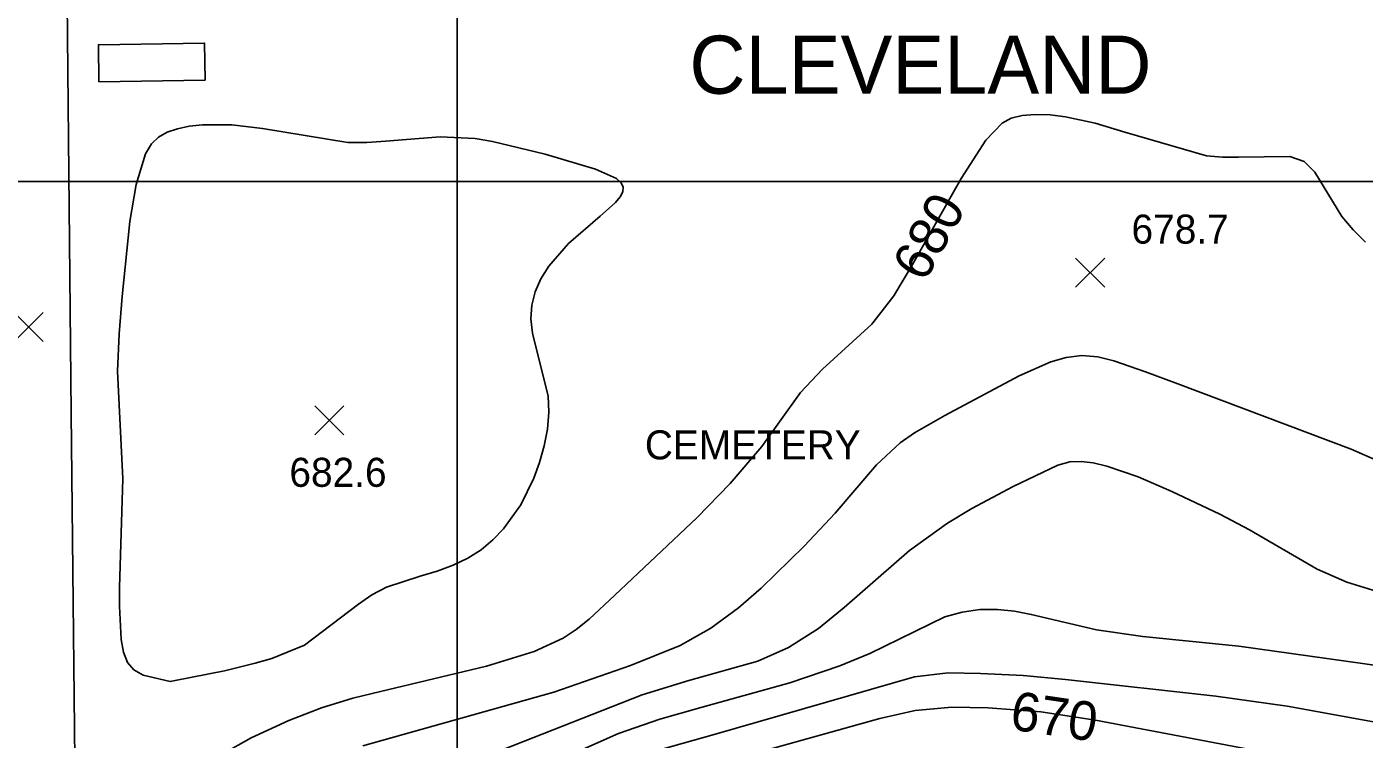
# Model space of a CAD drawing. Extents: x 79600 to 91800, y 75600 to 84400.
# Drawn here: x 80778 to 81468, y 78712 to 79080 of the extents above; entities that cross this region are included whole.
import ezdxf

# ---------------------------------------------------------------- set-up
doc = ezdxf.new("R2010")
doc.units = 0
for name, color, linetype in [('080-085$0$BLDG', 7, 'Continuous'), ('080-085$0$CITY-NAME', 7, 'Continuous'), ('080-085$0$GRID', 7, 'Continuous'), ('080-085$0$INDEX', 7, 'Continuous'), ('080-085$0$INDXLBL', 7, 'Continuous'), ('080-085$0$INTER', 7, 'Continuous'), ('080-085$0$ROAD', 7, 'Continuous'), ('080-085$0$ROAD-NAME', 7, 'Continuous'), ('080-085$0$SPOTMARK', 7, 'Continuous'), ('080-085$0$SPOTS', 7, 'Continuous')]:
    doc.layers.add(name, color=color, linetype=linetype)

# ---------------------------------------------------------------- blocks, each defined once
blk = doc.blocks.new('080-085$0$SPOTS')
at = {"layer": '080-085$0$SPOTMARK'}
for p, q in [((-0.5, -0.5), (0.5, 0.5)), ((-0.5, 0.5), (0.5, -0.5))]:
    blk.add_line(p, q, dxfattribs=at)

msp = doc.modelspace()

# ---------------------------------------------------------------- linework, layer by layer
at = {"layer": '080-085$0$BLDG'}
msp.add_lwpolyline([(80869.76, 79052.42), (80814.93, 79051.58), (80814.64, 79070.71), (80869.47, 79071.55)], close=True, dxfattribs=at)
at = {"layer": '080-085$0$GRID'}
for p, q in [((81000, 80000), (81000, 76000)), ((85000, 79000), (80000, 79000))]:
    msp.add_line(p, q, dxfattribs=at)
at = {"layer": '080-085$0$INDEX'}
for points in [[(81468.93, 78968.77), (81462.51, 78975.14), (81456.65, 78982.05), (81442.84, 79004.95), (81437.28, 79010.4), (81429.83, 79013.02), (81403.43, 79012.61), (81395.11, 79012.62), (81386.77, 79013.39), (81344.64, 79025.52), (81329.28, 79030.14), (81313.97, 79033.52), (81306.04, 79034.44), (81298.38, 79034.69), (81291.58, 79034.15), (81286.04, 79032.7), (81281.42, 79030.18), (81272.9, 79021.34), (81260.14, 79001.68), (81235.02, 78957.13), (81225.32, 78941.03), (81214.04, 78926.43), (81188.5, 78903.15), (81177.14, 78891.11), (81157.18, 78863.17), (81140.89, 78844.15), (81123.63, 78826.43), (81081.25, 78786.47), (81068.07, 78773.95), (81061.45, 78768.7), (81054.67, 78764.25), (81039.72, 78757.27), (81015.08, 78749.67), (80960.34, 78736.59), (80946.04, 78733.16), (80929.87, 78728.24), (80912.97, 78721.72), (80893.61, 78712.72), (80865.53, 78696.92)], [(81431.15, 78702.63), (81329.57, 78721.79), (81301.32, 78726.15), (81274.15, 78728.23), (81255.41, 78728.59), (81236.36, 78726.78), (81218.14, 78722.75), (81130.54, 78698.26)]]:
    msp.add_lwpolyline(points, dxfattribs=at)
at = {"layer": '080-085$0$INTER'}
msp.add_lwpolyline([(80854.34, 78742.28), (80879.81, 78747.39), (80895.7, 78751.36), (80904.24, 78753.77), (80921.11, 78760.51), (80948.96, 78781.69), (80955.85, 78786.54), (80963.41, 78790.59), (80980.81, 78796.29), (80989.65, 78798.85), (80997.89, 78801.86), (81005.44, 78805.48), (81012.28, 78809.84), (81018.42, 78814.98), (81023.88, 78820.71), (81032.78, 78833), (81039.59, 78846.83), (81042.48, 78854.87), (81044.88, 78863.46), (81046.54, 78872.23), (81047.27, 78880.86), (81046.98, 78889.33), (81040.78, 78914.03), (81038.75, 78921.79), (81037.93, 78929.17), (81038.42, 78936.22), (81040.18, 78943.09), (81043.17, 78949.83), (81047.19, 78956.34), (81057.46, 78968.1), (81073.84, 78982.09), (81081.75, 78989.21), (81084.13, 78992.13), (81085.39, 78994.72), (81085.56, 78997.09), (81084.59, 78999.34), (81082.16, 79001.58), (81071.4, 79006.4), (81045.41, 79014.13), (81018.12, 79020.7), (81009.16, 79022.22), (80991.13, 79023.2), (80962.94, 79020.93), (80953.21, 79020.28), (80943.46, 79020.28), (80899.37, 79027.49), (80883.64, 79029.31), (80868.4, 79029.4), (80861.56, 79028.65), (80855.45, 79027.36), (80850.17, 79025.51), (80845.76, 79023.03), (80842.11, 79019.47), (80839.04, 79014.29), (80834.22, 78998.53), (80830.97, 78979.36), (80826.97, 78940.75), (80825.45, 78921.41), (80824.58, 78902.15), (80827.24, 78846.44), (80825.62, 78790.39), (80825.58, 78780.72), (80826.49, 78763.5), (80827.63, 78756.88), (80829.65, 78751.69), (80832.99, 78747.81), (80837.81, 78745.12), (80851.71, 78741.86)], close=True, dxfattribs=at)
for points in [[(81492.49, 78848.14), (81461.59, 78861.87), (81372.02, 78895.56), (81355.42, 78901.77), (81338.98, 78907.42), (81330.67, 78909.45), (81322.45, 78910.19), (81314.4, 78909.24), (81306.42, 78906.88), (81290.17, 78899.75), (81251.77, 78879.26), (81236.08, 78870.18), (81228.72, 78865.09), (81216.38, 78853.69), (81195.19, 78828.77), (81179.13, 78811.63), (81156.97, 78790.05), (81145.22, 78779.81), (81130.96, 78769.31), (81115.09, 78760.34), (81089.47, 78750.1), (81049.84, 78736.28), (80951.16, 78708.5)], [(81475.02, 78788.31), (81459.26, 78793.06), (81443.96, 78799.91), (81408.97, 78820.12), (81393.68, 78828.31), (81369, 78840.02), (81351.59, 78847.48), (81335.33, 78853), (81328.29, 78854.68), (81322.15, 78855.48), (81316.34, 78855.19), (81310.09, 78853.6), (81287, 78842.58), (81265.67, 78831.13), (81253.1, 78823.6), (81233.49, 78809.42), (81199.67, 78780.02), (81186.42, 78769.2), (81170.97, 78759.37), (81155.22, 78752.35), (81119.49, 78742.32), (81095.44, 78735), (81023.69, 78706.74)], [(81477.18, 78749.67), (81403.53, 78760.14), (81353.93, 78765.09), (81329.98, 78768.55), (81296.38, 78776.45), (81287.71, 78778.06), (81278.87, 78779), (81269.85, 78778.94), (81260.7, 78777.66), (81251.68, 78775.29), (81213.06, 78756.33), (81197.5, 78749.88), (81171.73, 78741.04), (81126.44, 78728.52), (81104.61, 78722.28), (81083.22, 78714.98), (81017.6, 78685.84)], [(81526.75, 78711.46), (81522.15, 78714.26), (81480.69, 78719.67), (81428.46, 78728.99), (81391.62, 78734.22), (81314.06, 78742.86), (81292.16, 78744.88), (81270.2, 78746.03), (81253.4, 78746.21), (81236.04, 78744.25), (81132.66, 78714.51), (81099.62, 78705.21)]]:
    msp.add_lwpolyline(points, dxfattribs=at)
at = {"layer": '080-085$0$ROAD'}
msp.add_lwpolyline([(80803.08, 78652.42), (80800.65, 78880.38), (80797.61, 79181.46)], dxfattribs=at)

# ---------------------------------------------------------------- block references
at = {"layer": '080-085$0$SPOTMARK', "xscale": 15, "yscale": 15}
for p in [(81326.78, 78952.98), (80778.68, 78924.95), (80933.91, 78876.71)]:
    msp.add_blockref('080-085$0$SPOTS', p, dxfattribs=at)

# ---------------------------------------------------------------- texts
at = {"layer": '080-085$0$CITY-NAME'}
msp.add_text('CLEVELAND', height=30, dxfattribs=at).set_placement((81119.84, 79045.4))
at = {"layer": '080-085$0$INDXLBL'}
for s, rotation, p in [('680', 60.87168, (81241.26, 78947.44)), ('670', 351.6408, (81284.76, 78717.18))]:
    msp.add_text(s, height=20, rotation=rotation, dxfattribs=at).set_placement(p)
at = {"layer": '080-085$0$ROAD-NAME'}
msp.add_text('CEMETERY', height=15, dxfattribs=at).set_placement((81096.83, 78856.54))
at = {"layer": '080-085$0$SPOTS'}
for s, p in [('678.7', (81348.13, 78967.98)), ('682.6', (80913.29, 78842.36))]:
    msp.add_text(s, height=15, dxfattribs=at).set_placement(p)

doc.saveas('drawing.dxf')
